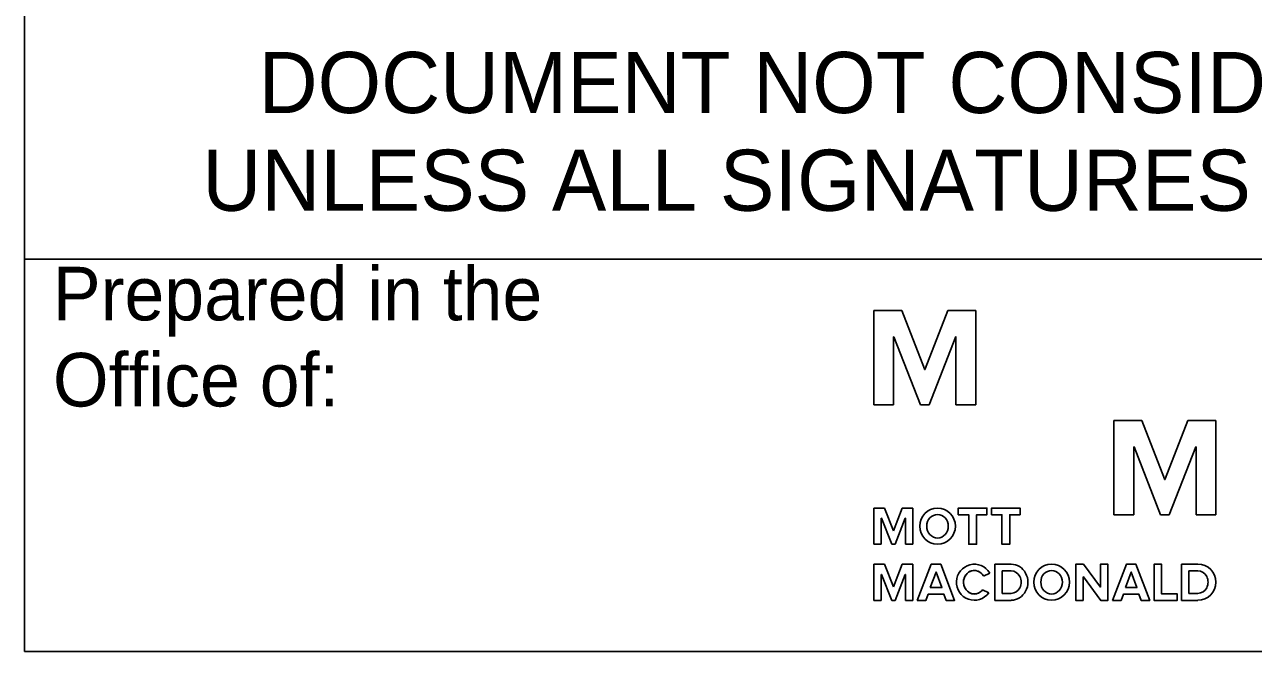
# Model space of a CAD drawing. Extents: x 1901718 to 1902220, y 193828 to 194187.
# Drawn here: x 1902112.54 to 1902123.6, y 193914.63 to 193920.27 of the extents above; entities that cross this region are included whole.
import ezdxf

# ---------------------------------------------------------------- set-up
doc = ezdxf.new("R2010")
doc.units = 0
for name, color, linetype in [('Old_Level_2', 7, 'Continuous'), ('Old_Level_42', 7, 'Continuous'), ('Sheet Sticker Exception Certification CELL', 7, 'Continuous')]:
    doc.layers.add(name, color=color, linetype=linetype)

msp = doc.modelspace()

# ---------------------------------------------------------------- linework, layer by layer
at = {"layer": 'Old_Level_2'}
for p, q in [((1902120.437, 193917.699), (1902120.185, 193917.699)), ((1902120.185, 193917.699), (1902120.185, 193916.849)), ((1902120.642, 193917.174), (1902120.437, 193917.699)), ((1902120.853, 193917.699), (1902120.647, 193917.174)), ((1902121.105, 193917.699), (1902120.853, 193917.699)), ((1902121.105, 193916.849), (1902121.105, 193917.699)), ((1902120.364, 193916.849), (1902120.364, 193917.46)), ((1902120.364, 193917.46), (1902120.366, 193917.46)), ((1902120.366, 193917.46), (1902120.606, 193916.849)), ((1902120.684, 193916.849), (1902120.923, 193917.463)), ((1902120.923, 193917.463), (1902120.925, 193917.463)), ((1902120.925, 193917.463), (1902120.925, 193916.849)), ((1902120.642, 193917.166), (1902120.642, 193917.174)), ((1902120.647, 193917.166), (1902120.642, 193917.166)), ((1902120.647, 193917.174), (1902120.647, 193917.166)), ((1902120.185, 193916.849), (1902120.364, 193916.849)), ((1902120.606, 193916.849), (1902120.684, 193916.849)), ((1902120.925, 193916.849), (1902121.105, 193916.849)), ((1902122.598, 193916.709), (1902122.346, 193916.709)), ((1902122.346, 193916.709), (1902122.346, 193915.859)), ((1902122.803, 193916.184), (1902122.598, 193916.709)), ((1902123.014, 193916.709), (1902122.809, 193916.184)), ((1902123.266, 193916.709), (1902123.014, 193916.709)), ((1902123.266, 193915.859), (1902123.266, 193916.709)), ((1902122.525, 193915.859), (1902122.525, 193916.47)), ((1902122.525, 193916.47), (1902122.528, 193916.47)), ((1902122.528, 193916.47), (1902122.767, 193915.859)), ((1902122.845, 193915.859), (1902123.084, 193916.472)), ((1902123.084, 193916.472), (1902123.087, 193916.472)), ((1902123.087, 193916.472), (1902123.087, 193915.859)), ((1902122.803, 193916.176), (1902122.803, 193916.184)), ((1902122.809, 193916.176), (1902122.803, 193916.176)), ((1902122.809, 193916.184), (1902122.809, 193916.176)), ((1902120.281, 193915.919), (1902120.185, 193915.919)), ((1902120.185, 193915.919), (1902120.185, 193915.594)), ((1902120.361, 193915.716), (1902120.281, 193915.919)), ((1902120.442, 193915.919), (1902120.361, 193915.716)), ((1902120.538, 193915.919), (1902120.442, 193915.919)), ((1902120.538, 193915.594), (1902120.538, 193915.919)), ((1902120.538, 193915.594), (1902120.538, 193915.919)), ((1902120.252, 193915.594), (1902120.252, 193915.828)), ((1902120.252, 193915.828), (1902120.255, 193915.828)), ((1902120.252, 193915.828), (1902120.255, 193915.828)), ((1902120.255, 193915.828), (1902120.346, 193915.594)), ((1902120.377, 193915.594), (1902120.468, 193915.828)), ((1902120.468, 193915.828), (1902120.47, 193915.828)), ((1902120.468, 193915.828), (1902120.47, 193915.828)), ((1902120.468, 193915.828), (1902120.47, 193915.828)), ((1902120.47, 193915.828), (1902120.471, 193915.594)), ((1902122.346, 193915.859), (1902122.525, 193915.859)), ((1902122.767, 193915.859), (1902122.845, 193915.859)), ((1902123.087, 193915.859), (1902123.266, 193915.859)), ((1902120.185, 193915.594), (1902120.252, 193915.594)), ((1902120.346, 193915.594), (1902120.377, 193915.594)), ((1902120.471, 193915.594), (1902120.538, 193915.594)), ((1902120.281, 193915.414), (1902120.185, 193915.414)), ((1902120.185, 193915.414), (1902120.185, 193915.089)), ((1902120.252, 193915.089), (1902120.252, 193915.323)), ((1902120.252, 193915.323), (1902120.255, 193915.323)), ((1902120.255, 193915.323), (1902120.346, 193915.089)), ((1902120.361, 193915.211), (1902120.281, 193915.414)), ((1902120.442, 193915.414), (1902120.361, 193915.211)), ((1902120.377, 193915.089), (1902120.468, 193915.323)), ((1902120.538, 193915.414), (1902120.442, 193915.414)), ((1902120.468, 193915.323), (1902120.47, 193915.323)), ((1902120.47, 193915.323), (1902120.471, 193915.089)), ((1902120.538, 193915.089), (1902120.538, 193915.414)), ((1902121.172, 193915.308), (1902121.229, 193915.335)), ((1902121.172, 193915.308), (1902121.229, 193915.334)), ((1902121.422, 193915.414), (1902121.274, 193915.414)), ((1902121.274, 193915.414), (1902121.274, 193915.246)), ((1902121.341, 193915.152), (1902121.341, 193915.354)), ((1902121.341, 193915.354), (1902121.422, 193915.354)), ((1902122.955, 193915.414), (1902122.955, 193915.414)), ((1902123.104, 193915.414), (1902122.955, 193915.414)), ((1902122.955, 193915.414), (1902122.955, 193915.246)), ((1902123.023, 193915.152), (1902123.023, 193915.354)), ((1902123.023, 193915.354), (1902123.104, 193915.354)), ((1902123.104, 193915.352), (1902123.104, 193915.352)), ((1902121.274, 193915.246), (1902121.274, 193915.089)), ((1902122.955, 193915.246), (1902122.955, 193915.089)), ((1902121.221, 193915.156), (1902121.164, 193915.184)), ((1902121.221, 193915.156), (1902121.164, 193915.184)), ((1902121.422, 193915.152), (1902121.341, 193915.152)), ((1902123.104, 193915.152), (1902123.023, 193915.152)), ((1902120.185, 193915.089), (1902120.252, 193915.089)), ((1902120.346, 193915.089), (1902120.377, 193915.089)), ((1902120.471, 193915.089), (1902120.538, 193915.089)), ((1902121.274, 193915.089), (1902121.422, 193915.089)), ((1902122.955, 193915.089), (1902123.104, 193915.089))]:
    msp.add_line(p, q, dxfattribs=at)
for points in [[(1902120.946, 193915.859), (1902121.04, 193915.859), (1902121.04, 193915.594), (1902121.11, 193915.594), (1902121.11, 193915.859), (1902121.204, 193915.859), (1902121.204, 193915.919), (1902120.946, 193915.919), (1902120.946, 193915.859)], [(1902121.245, 193915.859), (1902121.339, 193915.859), (1902121.339, 193915.594), (1902121.409, 193915.594), (1902121.409, 193915.859), (1902121.502, 193915.859), (1902121.502, 193915.919), (1902121.245, 193915.919), (1902121.245, 193915.859)], [(1902120.577, 193915.089), (1902120.655, 193915.089), (1902120.676, 193915.144), (1902120.816, 193915.144), (1902120.837, 193915.089), (1902120.912, 193915.089), (1902120.788, 193915.414), (1902120.702, 193915.414), (1902120.577, 193915.089)], [(1902120.694, 193915.204), (1902120.746, 193915.344), (1902120.798, 193915.204), (1902120.694, 193915.204)], [(1902122.069, 193915.3), (1902122.072, 193915.3), (1902122.228, 193915.089), (1902122.293, 193915.089), (1902122.293, 193915.414), (1902122.225, 193915.414), (1902122.225, 193915.209), (1902122.072, 193915.414), (1902122.004, 193915.414), (1902122.004, 193915.089), (1902122.069, 193915.089), (1902122.069, 193915.3)], [(1902122.334, 193915.089), (1902122.412, 193915.089), (1902122.433, 193915.144), (1902122.573, 193915.144), (1902122.594, 193915.089), (1902122.67, 193915.089), (1902122.545, 193915.414), (1902122.459, 193915.414), (1902122.334, 193915.089)], [(1902122.451, 193915.204), (1902122.503, 193915.344), (1902122.555, 193915.204), (1902122.451, 193915.204)], [(1902122.917, 193915.089), (1902122.917, 193915.147), (1902122.776, 193915.147), (1902122.776, 193915.414), (1902122.709, 193915.414), (1902122.709, 193915.089), (1902122.917, 193915.089)], [(1902122.917, 193915.089), (1902122.917, 193915.147), (1902122.776, 193915.147), (1902122.776, 193915.414), (1902122.709, 193915.414), (1902122.709, 193915.089), (1902122.917, 193915.09), (1902122.917, 193915.147)]]:
    msp.add_lwpolyline(points, dxfattribs=at)
msp.add_arc((1902123.104, 193915.252), 0.162, 270, 90, dxfattribs=at)
for centre, major_axis, ratio in [((1902120.759, 193915.756), (0, 0.162), 0.993118), ((1902120.759, 193915.756), (0, 0.106), 0.916103), ((1902121.786, 193915.252), (0, 0.162), 0.993118), ((1902121.786, 193915.252), (0, 0.106), 0.916103)]:
    msp.add_ellipse(centre, major_axis=major_axis, ratio=ratio, dxfattribs=at)
for centre, major_axis, ratio, start_param, end_param in [((1902121.09, 193915.252), (0, 0.162), 0.993118, 5.246647, 10.366427), ((1902121.09, 193915.252), (0, 0.162), 0.993118, 5.246647, 10.366427), ((1902121.09, 193915.252), (0, 0.106), 0.916103, 5.276876, 9.424778), ((1902121.09, 193915.252), (0, 0.106), 0.916103, 5.276876, 10.296021), ((1902121.422, 193915.252), (0, -0.162), 0.930276, 0, 3.141593), ((1902121.422, 193915.253), (0, -0.101), 0.900832, 0, 3.141593), ((1902123.104, 193915.253), (0, -0.101), 0.900832, 0, 3.141593), ((1902121.09, 193915.252), (0, 0.106), 0.916103, 3.141593, 4.012835)]:
    msp.add_ellipse(centre, major_axis=major_axis, ratio=ratio, start_param=start_param, end_param=end_param, dxfattribs=at)
at = {"layer": 'Old_Level_42'}
msp.add_lwpolyline([(1902132.544, 193914.629), (1902112.539, 193914.629), (1902112.539, 193918.159)], dxfattribs=at)
at = {"layer": 'Sheet Sticker Exception Certification CELL'}
for p, q in [((1902112.539, 193918.159), (1902112.539, 193920.509)), ((1902132.542, 193918.159), (1902112.539, 193918.159))]:
    msp.add_line(p, q, dxfattribs=at)

# ---------------------------------------------------------------- texts
at = {"layer": 'Old_Level_2'}
for s, height, p in [('Prepared in the ', 0.48186, (1902112.794, 193917.609)), ('Office of:', 0.4819, (1902112.794, 193916.834))]:
    msp.add_text(s, height=height, dxfattribs=at).set_placement(p)
at = {"layer": 'Sheet Sticker Exception Certification CELL'}
for s, p in [('DOCUMENT NOT CONSIDERED FINAL', (1902114.646, 193919.475)), ('UNLESS ALL SIGNATURES COMPLETED', (1902114.139, 193918.595))]:
    msp.add_text(s, height=0.55, dxfattribs=at).set_placement(p)

doc.saveas('drawing.dxf')
